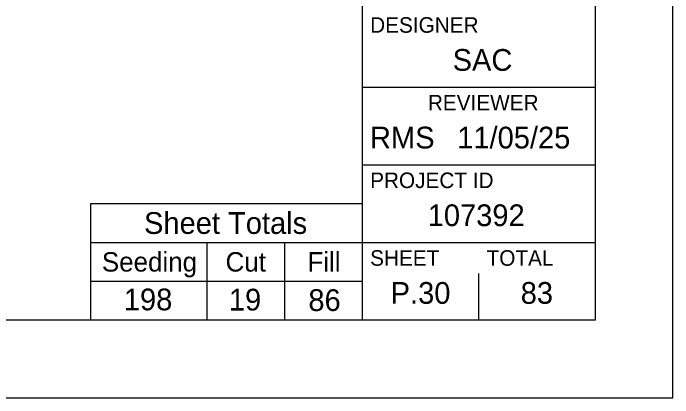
# Model space of a CAD drawing. Extents: x -31.8 to 34, y 0 to 22.
# Drawn here: x 29.75 to 34, y 0 to 2.476 of the extents above; entities that cross this region are included whole.
import ezdxf

# ---------------------------------------------------------------- set-up
doc = ezdxf.new("R2010")
doc.units = 0
for name, color, linetype in [('_CIVIL_CONSTRUCTION', 7, 'Continuous'), ('PF_X_Ground_Line', 7, 'Continuous'), ('SH_Text', 7, 'Continuous'), ('UT_X_FO', 7, 'Continuous')]:
    doc.layers.add(name, color=color, linetype=linetype)

msp = doc.modelspace()

# ---------------------------------------------------------------- linework, layer by layer
at = {"layer": '_CIVIL_CONSTRUCTION'}
for p, q in [((30.25, 0.5), (30.25, 1.25)), ((30.25, 1.25), (32, 1.25)), ((30.25, 1), (32, 1)), ((31, 0.5), (31, 1)), ((31.5, 0.5), (31.5, 1)), ((32.75, 0.5), (32.75, 0.8)), ((30.25, 0.75), (32, 0.75)), ((32.375, 0.675), (32.375, 0.675)), ((30.6316, 0.625), (30.6316, 0.625)), ((31.2545, 0.625), (31.2545, 0.625)), ((31.7599, 0.625), (31.7599, 0.625))]:
    msp.add_line(p, q, dxfattribs=at)
at = {"layer": 'PF_X_Ground_Line'}
for p, q in [((32, 0.5), (32, 21.5)), ((32, 2), (33.5, 2)), ((32, 1.5), (33.5, 1.5)), ((32, 1), (33.5, 1))]:
    msp.add_line(p, q, dxfattribs=at)
msp.add_lwpolyline([(1.5, 21.5), (33.5, 21.5), (33.5, 0.5), (1.5, 0.5)], close=True, dxfattribs=at)
at = {"layer": 'UT_X_FO'}
msp.add_lwpolyline([(0, 0), (34, 0), (34, 22), (0, 22)], close=True, dxfattribs=at)

# ---------------------------------------------------------------- texts
at = {"layer": '_CIVIL_CONSTRUCTION'}
for s, height, p in [('DESIGNER', 0.1, (32.05, 2.35)), ('SAC', 0.14, (32.5813, 2.105)), ('REVIEWER', 0.1, (32.4218, 1.85)), ('RMS', 0.14, (32.0491, 1.605)), ('11/05/25', 0.14, (32.611, 1.605)), ('PROJECT ID', 0.1, (32.05, 1.35)), ('107392', 0.14, (32.4209, 1.105)), ('Sheet Totals', 0.14, (30.5931, 1.055)), ('Seeding', 0.125, (30.3214, 0.8125)), ('Cut', 0.125, (31.1183, 0.8125)), ('Fill', 0.125, (31.6455, 0.8125)), ('SHEET', 0.1, (32.05, 0.85)), ('TOTAL', 0.1, (32.8, 0.85)), ('P.30', 0.14, (32.1822, 0.605)), ('83', 0.14, (33.02, 0.605))]:
    msp.add_text(s, height=height, dxfattribs=at).set_placement(p)
at = {"layer": 'SH_Text'}
for s, p in [('198', (30.463, 0.5631)), ('19', (31.1398, 0.5619)), ('86', (31.6519, 0.5588))]:
    msp.add_text(s, height=0.14, dxfattribs=at).set_placement(p)

doc.saveas('drawing.dxf')
